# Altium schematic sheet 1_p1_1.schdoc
size 440 x 318 mm
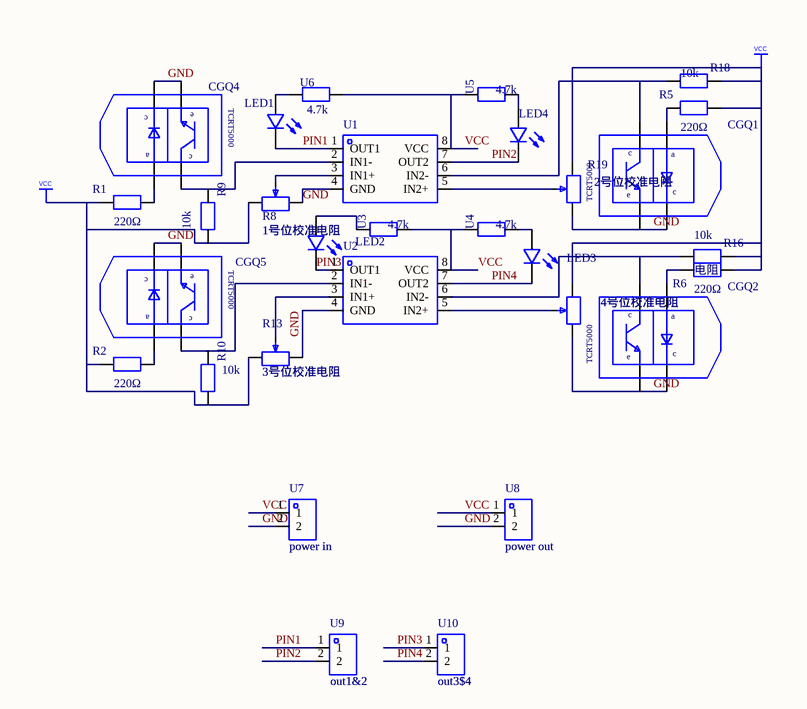
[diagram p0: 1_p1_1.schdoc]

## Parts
CGQ1  (no value)  [opto-th_tcrt5000l]
CGQ2  (no value)  [opto-th_tcrt5000l]
CGQ4  (no value)  [opto-th_tcrt5000l]
CGQ5  (no value)  [opto-th_tcrt5000l]
LED1  (no value)  [led-th_bd3.8-p2.54-fd]
LED2  (no value)  [led-th_bd3.8-p2.54-fd]
LED3  (no value)  [led-th_bd3.8-p2.54-fd]
LED4  (no value)  [led-th_bd3.8-p2.54-fd]
R1  value 220Ω  [直插电阻]
R2  value 220Ω  [直插电阻]
R5  value 220Ω  [直插电阻]
R6  value 220Ω  Symbol: 电阻  [直插电阻]
R8  1号位校准电阻  [res-adj-th_3296w]
R9  value 10k  [直插电阻]
R10  value 10k  [直插电阻]
R13  3号位校准电阻  [res-adj-th_3296w]
R16  value 10k  [直插电阻]
R18  value 10k  [直插电阻]
R19  2号位校准电阻  [res-adj-th_3296w]
R20  4号位校准电阻  [res-adj-th_3296w]
U1  (no value)  [dip-8_l9.7-w6.4-p2.54-ls7.6-bl]
U2  (no value)  [dip-8_l9.7-w6.4-p2.54-ls7.6-bl]
U3  value 4.7k  [res-th_bd5.5-l19.0-p23.00-d1.0]
U4  value 4.7k  [res-th_bd5.5-l19.0-p23.00-d1.0]
U5  value 4.7k  [res-th_bd5.5-l19.0-p23.00-d1.0]
U6  value 4.7k  [res-th_bd5.5-l19.0-p23.00-d1.0]
U7  power in  [hdr-th_2p-p2.54-v-m-1]
U8  power out  [hdr-th_2p-p2.54-v-m-1]
U9  out1&2  [hdr-th_2p-p2.54-v-m-1]
U10  out3$4  [hdr-th_2p-p2.54-v-m-1]

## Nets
VCC: R1.2 R2.2 R5.1 R6.1 R8.3 R9.1 R10.1 R13.3 R16.2 R18.2 R19.1 R20.1 U1.8(VCC) U2.8(VCC) U3.1 U4.2 U5.2 U6.2 U7.1 U8.1
GND: CGQ1.2(E) CGQ1.4(C) CGQ2.2(E) CGQ2.4(C) CGQ4.2(E) CGQ4.4(C) CGQ5.2(E) CGQ5.4(C) R8.1 R13.1 R19.3 R20.3 U1.4(GND) U2.4(GND) U7.2 U8.2
PIN1: LED1.2(C) U1.1(OUT1) U9.1
PIN2: LED4.2(C) U1.7(OUT2) U9.2
PIN3: LED2.2(C) U2.1(OUT1) U10.1
PIN4: LED3.2(C) U2.7(OUT2) U10.2
NetCGQ1_1: CGQ1.1(C) R18.1 U1.6(IN2-)
NetCGQ1_3: CGQ1.3(A) R5.2
NetCGQ2_1: CGQ2.1(C) R16.1 U2.6(IN2-)
NetCGQ2_3: CGQ2.3(A) R6.2
NetCGQ4_1: CGQ4.1(C) R9.2 U1.2(IN1-)
NetCGQ4_3: CGQ4.3(A) R1.1
NetCGQ5_1: CGQ5.1(C) R10.2 U2.2(IN1-)
NetCGQ5_3: CGQ5.3(A) R2.1
NetLED1_1: LED1.1(A) U6.1
NetLED2_1: LED2.1(A) U3.2
NetLED3_1: LED3.1(A) U4.1
NetLED4_1: LED4.1(A) U5.1
NetR8_2: R8.2 U1.3(IN1+)
NetR13_2: R13.2 U2.3(IN1+)
NetR19_2: R19.2 U1.5(IN2+)
NetR20_2: R20.2 U2.5(IN2+)

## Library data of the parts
CGQ1 CGQ2 CGQ4 CGQ5 = TCRT5000L: Manufacturer: VISHAY(威世); Add into BOM: yes; Description: 950 nm 60 mA Through Hole Reflective Optical Sensor with Transistor Output
LED1-LED4 = 204-10SDRD/S530-A3-L: Manufacturer: EVERLIGHT(台湾亿光); Add into BOM: yes; Emitted Color: 红灯; Description: 发光颜色:红灯;
R1 R2 R5 = 直插电阻: Symbol: 电阻; Convert to PCB: yes; Description: 220
R6 = 直插电阻: Convert to PCB: yes; Description: 220
R8 R13 R19 R20 = 精密可调电阻 3296W-1-304(300K): Symbol: precision adjustable resistance 3296w-1-304(300k); Add into BOM: yes; NAME: 3
R9 = 直插电阻: Symbol: 电阻; Convert to PCB: yes
R10 R16 R18 = 直插电阻10k: Convert to PCB: yes
U1 U2 = LM393N: Manufacturer: HGSEMI(华冠); Add into BOM: yes; Description: 比较器组数:-;电源电压:-;各通道供电电流:-;输出类型:-;传播延迟:-;
U3-U6 = OX472KE: Manufacturer: Ohmite; Add into BOM: yes; Tolerance: ±10%; Power(Watts): 1W; Temperature Coefficient: -1600ppm/~-1000ppm/; Description: 电阻类型:陶瓷电阻;阻值:4.7k;精度:±10%;功率:1W;温度系数:-1600ppm/~-1000ppm/;工作温度范围:-40~+220;
U7-U10 = HDR1X2: Add into BOM: yes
